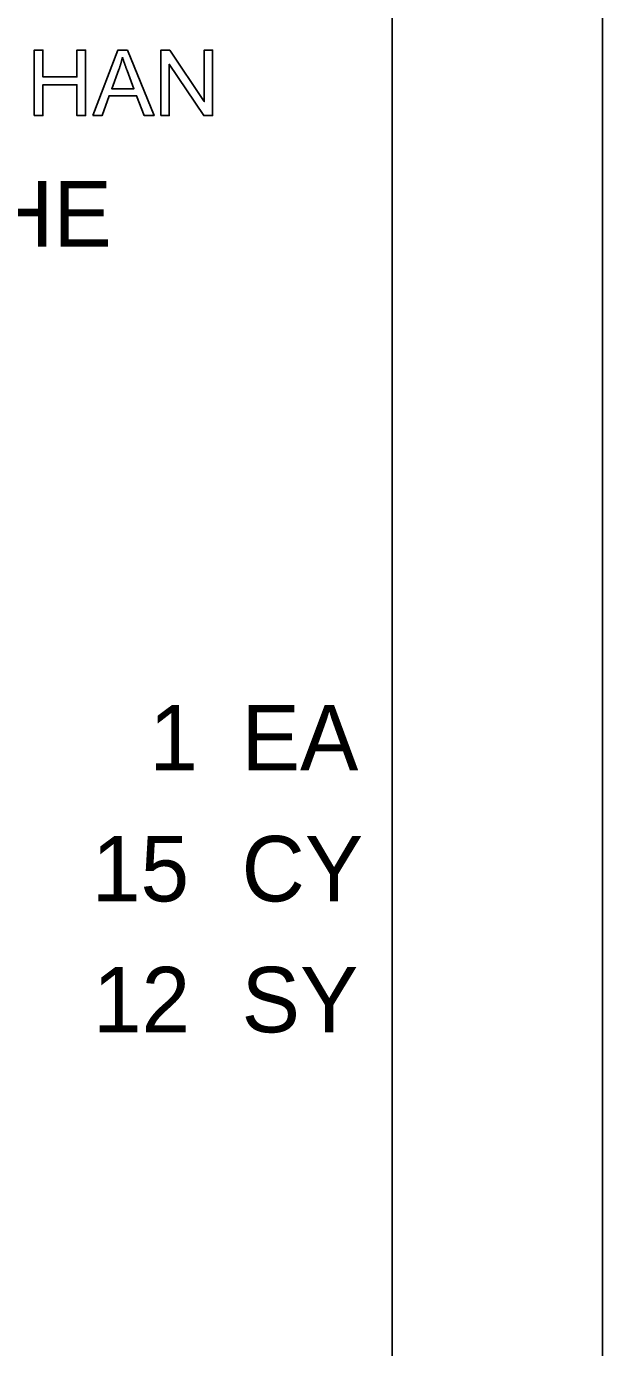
# Model space of a CAD drawing. Extents: x 12316 to 12541, y 1124 to 1850.
# Drawn here: x 12528.477 to 12529.709, y 1783.687 to 1786.512 of the extents above; entities that cross this region are included whole.
import ezdxf

# ---------------------------------------------------------------- set-up
doc = ezdxf.new("R2010")
doc.units = 0
for name, color, linetype in [('SC_Scratch1', 7, 'Continuous'), ('SH_Data', 7, 'Continuous'), ('SH_Text', 7, 'Continuous')]:
    doc.layers.add(name, color=color, linetype=linetype)

msp = doc.modelspace()

# ---------------------------------------------------------------- linework, layer by layer
at = {"layer": 'SC_Scratch1'}
for points in [[(12522.3694, 1789.3113), (12529.7094, 1789.3113), (12529.7094, 1769.1513), (12522.3694, 1769.1513)], [(12522.8194, 1789.3113), (12529.2594, 1789.3113), (12529.2594, 1769.1513), (12522.8194, 1769.1513)]]:
    msp.add_lwpolyline(points, close=True, dxfattribs=at)
at = {"layer": 'SH_Text'}
for points in [[(12528.4941, 1786.3212), (12528.4941, 1786.4612), (12528.5126, 1786.4612), (12528.5126, 1786.4037), (12528.5852, 1786.4037), (12528.5852, 1786.4612), (12528.6038, 1786.4612), (12528.6038, 1786.3212), (12528.5852, 1786.3212), (12528.5852, 1786.3871), (12528.5126, 1786.3871), (12528.5126, 1786.3212)], [(12528.6193, 1786.3212), (12528.639, 1786.3212), (12528.6543, 1786.3635), (12528.713, 1786.3635), (12528.7293, 1786.3212), (12528.7504, 1786.3212), (12528.6932, 1786.4612), (12528.6731, 1786.4612)], [(12528.765, 1786.3212), (12528.765, 1786.4612), (12528.784, 1786.4612), (12528.8576, 1786.3512), (12528.8576, 1786.4612), (12528.8753, 1786.4612), (12528.8753, 1786.3212), (12528.8564, 1786.3212), (12528.7827, 1786.4311), (12528.7827, 1786.3212)]]:
    msp.add_lwpolyline(points, close=True, dxfattribs=at)
msp.add_lwpolyline([(12528.6925, 1786.4175), (12528.7072, 1786.3786), (12528.6597, 1786.3786), (12528.6752, 1786.4197)], dxfattribs=at)
for points in [[(12528.6752, 1786.4197), (12528.6799, 1786.433), (12528.6827, 1786.4464)], [(12528.6827, 1786.4464), (12528.686, 1786.4352), (12528.6925, 1786.4175)]]:
    msp.add_open_spline(points, degree=2, dxfattribs=at)

# ---------------------------------------------------------------- texts
at = {"layer": 'SH_Data'}
for s, p in [('1', (12528.7403, 1784.9212)), ('EA', (12528.9375, 1784.9212)), ('15', (12528.6171, 1784.6412)), ('CY', (12528.9375, 1784.6412)), ('12', (12528.6194, 1784.3612)), ('SY', (12528.9375, 1784.3612))]:
    msp.add_text(s, height=0.14, dxfattribs=at).set_placement(p)
at = {"layer": 'SH_Text'}
msp.add_text('THE QUANTITIES HAVE BEEN PROVIDED AND CARRIED TO THE ', height=0.14, dxfattribs=at).set_placement((12522.8764, 1786.0412))

doc.saveas('drawing.dxf')
